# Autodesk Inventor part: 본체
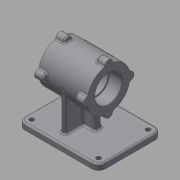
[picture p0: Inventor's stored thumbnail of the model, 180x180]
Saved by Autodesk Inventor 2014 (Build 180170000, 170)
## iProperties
Created: 2015-12
Part Number: 본체
Material: 일반
Document SubType Name: Modeling
Designer: USER
Density: 1 g/cm^3
Appearance: 기본값
Author: USER
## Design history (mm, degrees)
sketch "스케치1"
  geometry: L1 (-70, 55)-(70, 55); L2 (70, 55)-(70, -55); L3 (70, -55)-(-70, -55); L4 (-70, -55)-(-70, 55); L5 (-70, 55)-(70, -55); 2 further points
  constraints: 10 end point, 2 parallel, 1 coincident, 1 horizontal, 1 midpoint, 1 perpendicular
  dimensions: "d0" = 140 distance of L1.start L1.end; "d1" = 110 distance of L1.end L2.end
extrude "돌출1" new body sketch "스케치1" distance "d2" = 10; taper "d3" = 0 deg
sketch "스케치2"
  geometry: L1 (-32.5, 80)-(52.5, 80); L2 (-70, 0)-(-70, 10) reference; L3 (-70, 0)-(70, 0) reference; L4 (-32.5, 80)-(-32.5, 117); L5 (-32.5, 117)-(52.5, 117); L6 (52.5, 117)-(52.5, 80); 1 further point
  constraints: 8 end point, 2 perpendicular, 1 horizontal, 1 parallel
  dimensions: "d4" = 85 distance of L1.start L1.end; "d5" = 37.5 distance from line of L2 L1.start; "d6" = 80 distance between parallel lines of L3 L1; "d7" = 74 diameter of L5 L1
revolve "회전1" sketch "스케치2" stored, may be unused: angle "d8" = 90 deg
sketch "스케치3"
  geometry: L1 (70, -55)-(70, 55) reference; L2 (-6, -37)-(-14, -37); L3 (-14, -37)-(-14, 37); L4 (-14, 37)-(-6, 37); L5 (-6, 37)-(-6, -37); 3 further points
  constraints: 8 end point, 2 midpoint, 2 parallel, 1 horizontal, 1 horizontal alignment, 1 perpendicular
  dimensions: "d9" = 8 distance of L2.start L2.end; "d11" = 76 distance between parallel lines of L1 L5; "d13" = 74 distance between parallel lines of L4 L2
extrude "돌출2" join sketch "스케치3" stored distance "d14" = 10; taper "d15" = 0 deg
sketch "스케치4"
  geometry: L1 (-32.5, 43)-(52.5, 43) reference; L2 (70, 10)-(-70, 10) reference; L3 (-15, 10)-(-8.861, 60); L4 (-8.861, 60)-(28.861, 60); L5 (28.861, 60)-(35, 10); L6 (-70, 0)-(70, 0) reference; 2 further points
  constraints: 6 end point, 2 point on line, 1 midpoint, 1 parallel
  dimensions: "d16" = 25 horizontal distance of point (10, 43) L3.start; "d17" = 25 horizontal distance of point (10, 43) L5.end; "d18" = 60 distance between parallel lines of L6 L4; "d19" = 97 deg angle of L2 L5; "d20" = 97 deg angle of L2 L3
extrude "돌출3" join sketch "스케치4" stored distance "d21" = 12; taper "d22" = 0 deg
sketch "스케치6"
  geometry: C1 r 37 at (0, 0) reference; C2 r 23.5 at (0, 0); 1 further point
  constraints: 1 centre point, 1 coincident
  dimensions: "d26" = 47 diameter of C2
extrude "돌출5" cut sketch "스케치6" distance "d27" = 22; taper "d28" = 0 deg
sketch "스케치7"
  geometry: C1 r 23.5 at (0, 0) reference; C2 r 21 at (0, 0); 1 further point
  constraints: 1 centre point, 1 coincident
  dimensions: "d29" = 42 diameter of C2
extrude "돌출6" cut sketch "스케치7" distance "d30" = 41; taper "d31" = 0 deg
sketch "스케치8"
  geometry: C1 r 37 at (0, 0) reference; C2 r 23.5 at (0, 0); 1 further point
  constraints: 1 centre point, 1 coincident
  dimensions: "d32" = 47 diameter of C2
extrude "돌출7" cut sketch "스케치8" distance "d33" = 22; taper "d34" = 0 deg
fillet "모깎기1" dims "d35" = 0.3
chamfer "모따기1" distance "d36" = 1; stored, may be unused: second distance "d37" = 2, angle "d38" = 45 deg
chamfer "모따기2" distance "d39" = 1; stored, may be unused: second distance "d40" = 2, angle "d41" = 45 deg
sketch "스케치11"
  geometry: L1 (-70, -55)-(70, -55) reference; L2 (70, -55)-(70, 55) reference; L3 (-6, 37)-(-6, 6) reference; L4 (58, -43)-(-58, -43); C1 r 4 at (58, -43); C2 r 4 at (-58, -43); 1 further point
  constraints: 2 centre point, 2 end point, 1 perpendicular
  dimensions: "d45" = 8 diameter of C1; "d46" = 8 diameter of C2; "d47" = 116 distance of L4.start L4.end; "d48" = 12 distance from line of L2 L4.start; "d49" = 12 distance from line of L4.start L1
extrude "돌출9" cut sketch "스케치11" stored distance "d50" = 15; taper "d51" = 0 deg
fillet "모깎기2" dims "d52" = 12
fillet "모깎기3" dims "d53" = 3
fillet "모깎기4" dims "d54" = 3
sketch "스케치21"
  geometry: C1 r 7 at (37, 0); 2 further points
  constraints: 2 horizontal alignment, 1 centre point, 1 other
  dimensions: "d70" = 14 diameter of C1
extrude "돌출12" join sketch "스케치21" distance "d71" = 15; taper "d72" = 0 deg
node "작업 평면6"
sketch "스케치25"
  geometry: L1 (0, 0)-(0, 37); L2 (0, 0)-(-26.163, 26.163); A1 r 37 centre (0, 0) between (0, 37) and (-26.163, 26.163) reference; 2 further points
  constraints: 4 end point, 2 point on circle, 1 coincident, 1 vertical
  dimensions: "d80" = 45 deg angle of L1 L2
node "작업 평면7"
sketch "스케치26"
  geometry: L1 (-42.5, -37)-(-42.5, 37) reference; 3 further points
  constraints: 1 horizontal alignment, 1 midpoint, 1 other
  dimensions: "d81" = 42.5 distance from line of L1 point (0, 0)
extrude "돌출14" join sketch "스케치26" distance "d82" = 0.5; taper "d84" = 0 deg; dims "d83" = 1, "d85" = 0
sketch "스케치29"
  geometry: C1 r 7 at (-37, 0); 2 further points
  constraints: 2 horizontal alignment, 1 centre point, 1 other
  dimensions: "d91" = 14 diameter of C1
extrude "돌출16" join sketch "스케치29" distance "d92" = 15; taper "d93" = 0 deg
sketch "스케치31"
  geometry: C1 r 2 at (0, 0); A1 r 7 centre (0, 0) between (-0.662, -6.969) and (-0.662, 6.969) reference; 1 further point
  constraints: 1 centre point, 1 coincident
  dimensions: "d97" = 4 diameter of C1
hole "구멍1" sketch "스케치31" at (0, 0) diameter "d98" = 3.242; stored, may be unused: countersink angle "d102" = 90 deg, drill point angle "d104" = 118 deg; dims "d99" = 9, "d100" = 4, "d101" = 2, "d103" = 11
node "작업 평면8"
fillet "모깎기7" dims "d109" = 3
fillet "모깎기8" dims "d113" = 3
node "솔리드1"
mirror "대칭1"
pattern_circular "원형 패턴1" dims angle "d95" = 360 deg
pattern_circular "원형 패턴2" dims angle "d106" = 360 deg
mirror "대칭2"
pattern_circular "원형 패턴3" dims angle "d111" = 360 deg
pattern_circular "원형 패턴4" dims angle "d115" = 360 deg
